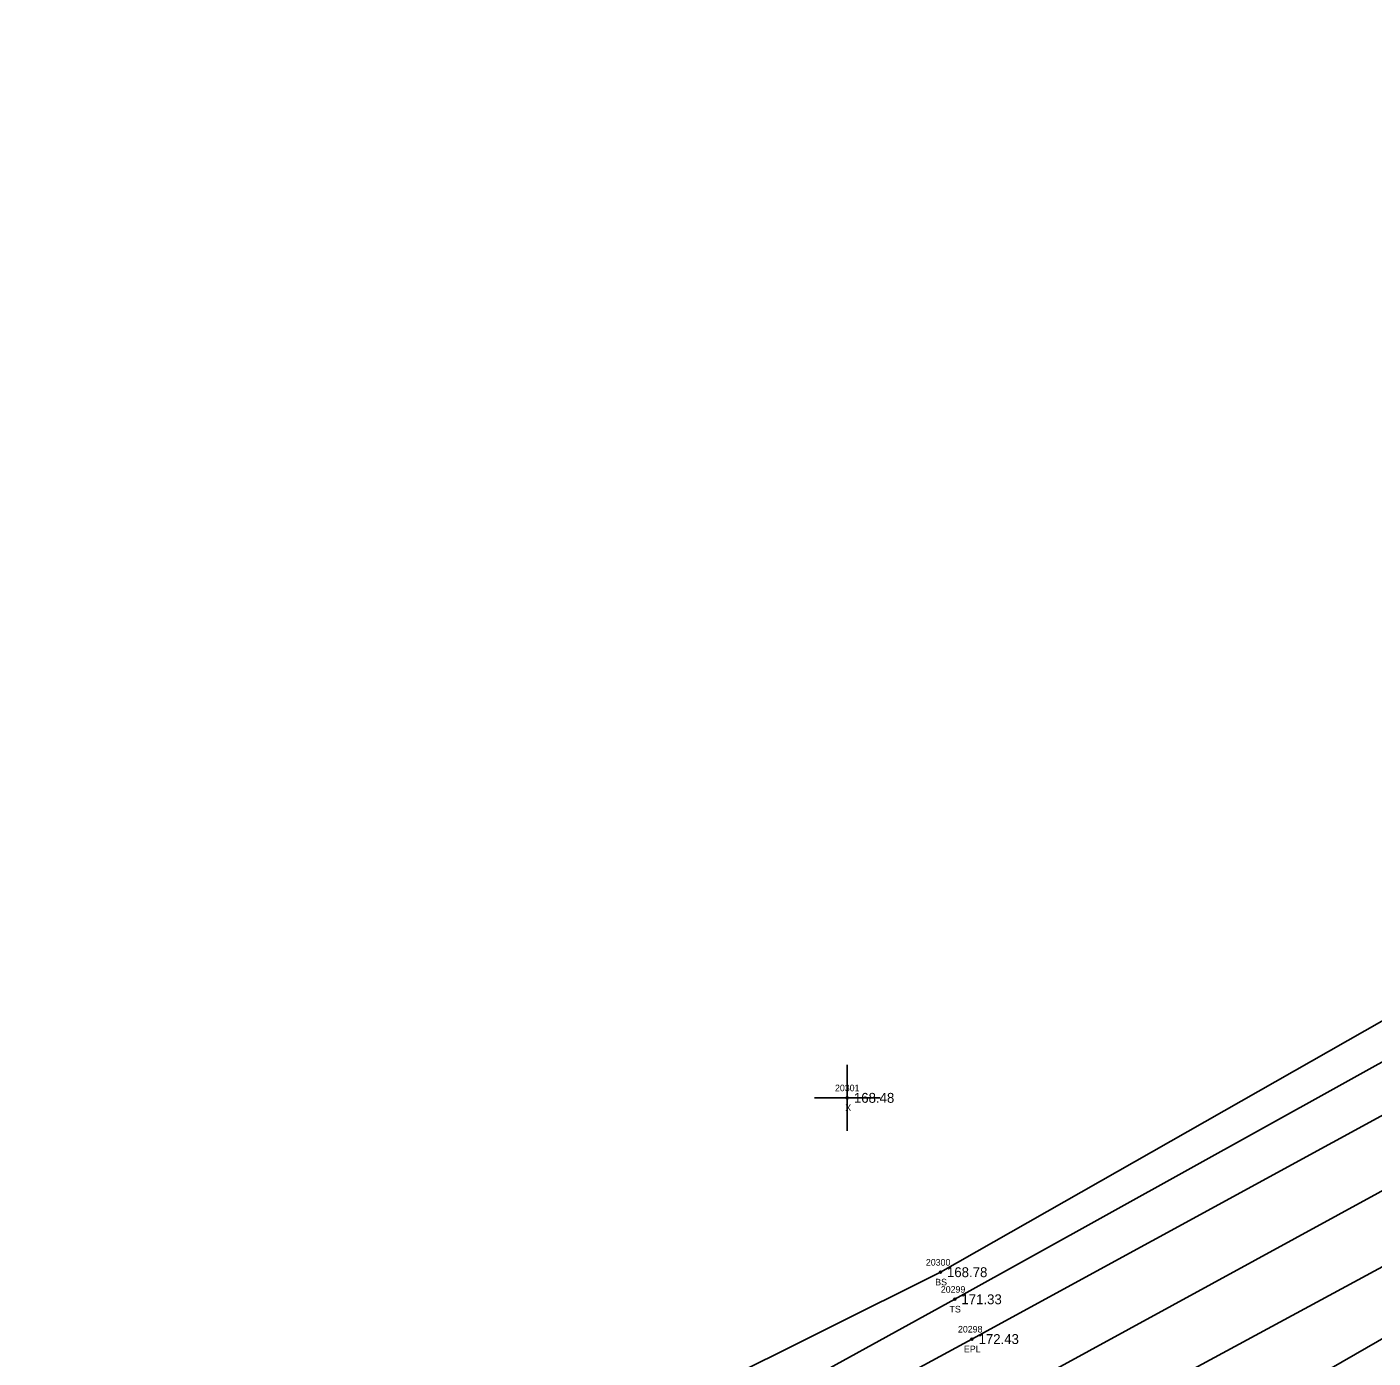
# Model space of a CAD drawing. Extents: x 2279528 to 2280976, y 1061373 to 1062235.
# Drawn here: x 2280424.4 to 2280628.7, y 1061988.9 to 1062190.9 of the extents above; entities that cross this region are included whole.
import ezdxf

# ---------------------------------------------------------------- set-up
doc = ezdxf.new("R2010")
doc.units = 0
for name, color, linetype in [('RD_DTM_BkLn1', 7, 'Continuous'), ('RD_DTM_BkLn2', 7, 'Continuous'), ('RD_DTM_BkLn_txCode', 7, 'Continuous'), ('RD_EX_Misc', 7, 'Continuous'), ('RD_EX_Misc_txCode', 7, 'Continuous'), ('RD_EX_Road', 7, 'Continuous'), ('RD_EX_Road_txCode', 7, 'Continuous'), ('RD_EX_TX_Misc_ELEV', 7, 'Continuous'), ('RD_EX_TX_Road_ELEV', 7, 'Continuous'), ('RD_SMD_Locator', 7, 'Continuous')]:
    doc.layers.add(name, color=color, linetype=linetype)

msp = doc.modelspace()

# ---------------------------------------------------------------- linework, layer by layer
at = {"layer": 'RD_DTM_BkLn1'}
msp.add_lwpolyline([(2279559.79, 1061433.13), (2279641.23, 1061477.49), (2279727.93, 1061524.84), (2279814.76, 1061571.75), (2279901.26, 1061618.64), (2279982.8, 1061662.56), (2280064.7, 1061706.86), (2280148.08, 1061751.86), (2280234.22, 1061798.46), (2280310.96, 1061840.01), (2280397.69, 1061887.57), (2280487.27, 1061936.5), (2280573.03, 1061983.12), (2280654.64, 1062027.66), (2280741.28, 1062074.45), (2280833.39, 1062123.87), (2280892.52, 1062155.9), (2280939.46, 1062181.85)], dxfattribs=at)
at = {"layer": 'RD_DTM_BkLn2'}
for points in [[(2280244.17, 1061836.72), (2280279.92, 1061859.99), (2280384.06, 1061910.85), (2280474.95, 1061958.02), (2280563.04, 1062001.93), (2280638.18, 1062044.64), (2280638.45, 1062052), (2280636.3, 1062090.14)], [(2280254.15, 1061833.04), (2280297.35, 1061859.31), (2280389.94, 1061901.4), (2280479.75, 1061950.78), (2280565.23, 1061997.82), (2280647.02, 1062043.23), (2280646.04, 1062059.26), (2280636.3, 1062090.14)], [(2280272.88, 1061795.9), (2280297.58, 1061791.78), (2280309.49, 1061810.68), (2280320.64, 1061820.76), (2280406.65, 1061872.9), (2280496.79, 1061919.98), (2280582.43, 1061964.41), (2280663.95, 1062011.32), (2280685.25, 1062021.45), (2280750.74, 1062056.04), (2280766.13, 1062062.47), (2280799.22, 1062079.83)]]:
    msp.add_lwpolyline(points, dxfattribs=at)
at = {"layer": 'RD_EX_Misc'}
for p, q in [((2280548.91, 1062023.39), (2280548.91, 1062033.39)), ((2280543.91, 1062028.39), (2280553.91, 1062028.39))]:
    msp.add_line(p, q, dxfattribs=at)
at = {"layer": 'RD_EX_Road'}
for points in [[(2279554.31, 1061441.46), (2279636.61, 1061486.51), (2279673.46, 1061506.76), (2279683.06, 1061512.21), (2279723.14, 1061533.54), (2279809.28, 1061580.29), (2279896.91, 1061627.91), (2279977.07, 1061671.02), (2280059.64, 1061715.57), (2280142.91, 1061760.72), (2280228.83, 1061807.06), (2280306.04, 1061849.18), (2280392.98, 1061896.71), (2280482.82, 1061945.75), (2280567.83, 1061991.78), (2280649.94, 1062036.55), (2280660.56, 1062042.19), (2280676.12, 1062050.66), (2280737.28, 1062083.64), (2280828.54, 1062132.77), (2280887.86, 1062164.61), (2280934.91, 1062190.9)], [(2280403.05, 1061879.04), (2280492, 1061927.92), (2280577.25, 1061974.17), (2280660.08, 1062018.91), (2280745.99, 1062065.19), (2280838.21, 1062115.39), (2280896.66, 1062146.92), (2280943.94, 1062172.8)]]:
    msp.add_lwpolyline(points, dxfattribs=at)
at = {"layer": 'RD_SMD_Locator'}
for centre in [(2280548.91, 1062028.39), (2280563.04, 1062001.93), (2280565.23, 1061997.82), (2280567.83, 1061991.78)]:
    msp.add_circle(centre, 0.15, dxfattribs=at)

# ---------------------------------------------------------------- texts
at = {"layer": 'RD_DTM_BkLn_txCode'}
for s, p in [('20300', (2280560.84, 1062002.93)), ('BS', (2280562.26, 1061999.93)), ('20299', (2280563.11, 1061998.82)), ('TS', (2280564.43, 1061995.82))]:
    msp.add_text(s, height=1, dxfattribs=at).set_placement(p)
at = {"layer": 'RD_EX_Misc_txCode'}
for s, p in [('20301', (2280547.04, 1062029.39)), ('X', (2280548.6, 1062026.39))]:
    msp.add_text(s, height=1, dxfattribs=at).set_placement(p)
at = {"layer": 'RD_EX_Road_txCode'}
for s, p in [('20298', (2280565.71, 1061992.78)), ('EPL', (2280566.62, 1061989.78))]:
    msp.add_text(s, height=1, dxfattribs=at).set_placement(p)
at = {"layer": 'RD_EX_TX_Misc_ELEV'}
for s, p in [('168.48', (2280549.91, 1062027.64)), ('168.78', (2280564.04, 1062001.18)), ('171.33', (2280566.23, 1061997.07))]:
    msp.add_text(s, height=1.5, dxfattribs=at).set_placement(p)
at = {"layer": 'RD_EX_TX_Road_ELEV'}
msp.add_text('172.43', height=1.5, dxfattribs=at).set_placement((2280568.83, 1061991.03))

doc.saveas('drawing.dxf')
